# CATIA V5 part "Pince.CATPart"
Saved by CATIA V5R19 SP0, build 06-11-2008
Part number: Pince
Publications: "e", "Lp", "Pp", "r"
Bounding box of the stored display mesh (mm): x -80 to 0, y 0 to 40, z 0 to 10
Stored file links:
  G:\EU_thinkMotion\CFAO_2010\MMS_groupe3\MMS_groupe3\A reprendre\evulliez\evulliez\Pince.CATPart
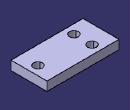
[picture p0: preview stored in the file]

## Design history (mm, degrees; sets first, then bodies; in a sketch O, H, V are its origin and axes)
Parameters
  e = 10 mm
  Lp = 40 mm
  Pp = 80 mm
  r = 5 mm
Body1 (main body)
  Sketch1 on yz-plane, origin (0, 0, 0), H (0, 1, 0), V (0, 0, 1)
    line L1 (0, 0) -> (40, 0)
    line L2 (40, 0) -> (40, 10)
    line L3 (40, 10) -> (0, 10)
    line L4 (0, 10) -> (0, 0)
    length L3 = 40 {= Lp}
    length L2 = 10 {= e}
    horizontal: L1 H, L3 H
    vertical: L2 V, L4 V
  Pad1: profile Sketch1, direction (-1, 0, 0), length 80 {= Pp}
  Point1: type OnPlane, Support face of Pad1 from Sketch1.L1, H -10, V -20 {= -Lp /2}, Direction (1, 0, 0)
  Sketch2 on face of Pad1 from Sketch1.L1, origin (-10, 20, 0), H (1, 0, 0), V (0, -1, 0)
    point P1 (0, 0)
    reference projected point E1 (0, 0) from Point1
    coincidence: E1 P1
  Hole1: placed by Sketch2, at (-10, 20, 0) direction (0, 0, 1), diameter 10 {= 2*r}, through (limit type 3)
  Point2: type OnPlane, Support face of Pad1 from Sketch1.L1, H -60 {= -(Pp -20mm)}, V -10, Direction (1, 0, 0)
  Point3: type OnPlane, Support face of Pad1 from Sketch1.L1, H -60 {= -(Pp -20mm)}, V -30 {= -(Lp -10mm)}, Direction (1, 0, 0)
  Sketch3 on face of Pad1 from Sketch1.L1, origin (-60, 10, 0), H (1, 0, 0), V (0, -1, 0)
    point P1 (0, 0)
    reference projected point E1 (0, 0) from Point2
    coincidence: E1 P1
  Hole2: placed by Sketch3, at (-60, 10, 0) direction (0, 0, 1), diameter 10, through (limit type 3)
  Sketch4 on face of Pad1 from Sketch1.L1, origin (-60, 30, 0), H (1, 0, 0), V (0, -1, 0)
    point P1 (0, 0)
    reference projected point E1 (0, 0) from Point3
    coincidence: E1 P1
  Hole3: placed by Sketch4, at (-60, 30, 0) direction (0, 0, 1), diameter 10, through (limit type 3)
